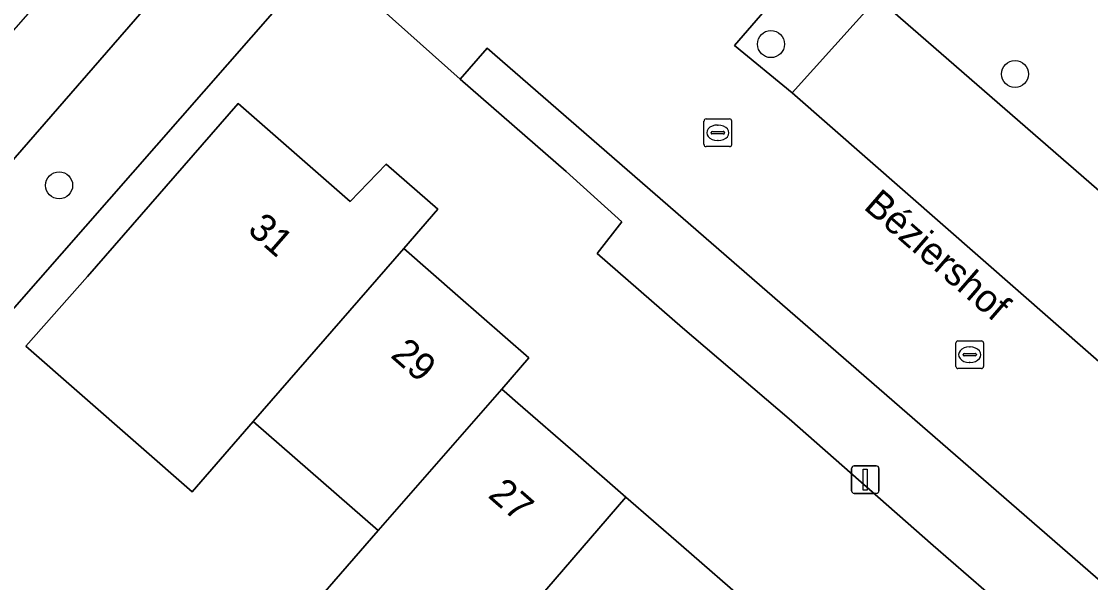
# Model space of a CAD drawing. Extents: x 158472 to 159562, y 388525 to 389606.
# Drawn here: x 158911.21 to 158949.88, y 388805.54 to 388825.82 of the extents above; entities that cross this region are included whole.
import ezdxf

# ---------------------------------------------------------------- set-up
doc = ezdxf.new("R2010")
doc.units = 0
for name, color, linetype in [('IMGEO_Boom', 7, 'Continuous'), ('IMGEO_Erf', 7, 'Continuous'), ('IMGEO_Fietspad_gesloten', 7, 'Continuous'), ('IMGEO_Groenvoorziening', 7, 'Continuous'), ('IMGEO_Haag', 7, 'Continuous'), ('IMGEO_Kolk', 7, 'Continuous'), ('IMGEO_Lichtmast', 7, 'Continuous'), ('IMGEO_Openbare_ruimte_label', 7, 'Continuous'), ('IMGEO_Pand', 7, 'Continuous'), ('IMGEO_Pand_nummerreeks', 7, 'Continuous'), ('IMGEO_Parkeervlak_open', 7, 'Continuous'), ('IMGEO_Rijbaan_lokaal_open', 7, 'Continuous'), ('IMGEO_Voetpad_open', 7, 'Continuous')]:
    doc.layers.add(name, color=color, linetype=linetype)

msp = doc.modelspace()

# ---------------------------------------------------------------- linework, layer by layer
at = {"layer": 'IMGEO_Boom'}
for centre in [(158938.319, 388825.003), (158947.149, 388823.921), (158912.572, 388819.898)]:
    msp.add_circle(centre, 0.489, dxfattribs=at)
at = {"layer": 'IMGEO_Erf'}
for points in [[(158948.022, 388803.56), (158944.187, 388806.882), (158938.98, 388811.457), (158935.123, 388814.752), (158932.03, 388817.43), (158932.924, 388818.579), (158930.914, 388820.395), (158927.08, 388823.739), (158924.182, 388826.315), (158922.086, 388828.178), (158895.45, 388797.816)], [(158920.505, 388803.282), (158924.117, 388807.418), (158919.597, 388811.364), (158917.382, 388808.826), (158911.364, 388814.08), (158913.593, 388816.605), (158919.045, 388822.851), (158923.096, 388819.313), (158924.4, 388820.668), (158926.271, 388819.033), (158925.036, 388817.62), (158926.999, 388815.907), (158929.568, 388813.664), (158928.581, 388812.533), (158928.766, 388812.372), (158929.162, 388812.027), (158931.246, 388810.215), (158933.067, 388808.632), (158935.074, 388806.887), (158937.593, 388804.696)]]:
    msp.add_lwpolyline(points, dxfattribs=at)
at = {"layer": 'IMGEO_Fietspad_gesloten'}
msp.add_lwpolyline([(158939.547, 388858.13), (158926.586, 388843.327), (158908.631, 388822.912), (158891.98, 388803.837), (158886.534, 388797.524), (158886.262, 388797.803), (158884.323, 388795.61), (158883.327, 388794.483), (158872.522, 388782.263), (158876.002, 388779.209), (158877.157, 388780.522), (158889.917, 388795.054), (158889.244, 388795.75), (158891.577, 388798.482), (158892.838, 388800.078), (158918.64, 388829.712), (158922.701, 388834.313), (158925.978, 388838.056), (158929.322, 388841.85), (158932.045, 388844.827), (158941.937, 388856.138)], dxfattribs=at)
at = {"layer": 'IMGEO_Groenvoorziening'}
msp.add_lwpolyline([(158918.64, 388829.712), (158892.838, 388800.078), (158895.45, 388797.816), (158922.086, 388828.178), (158920.255, 388829.805)], dxfattribs=at)
at = {"layer": 'IMGEO_Haag'}
msp.add_lwpolyline([(158918.64, 388829.712), (158892.838, 388800.078), (158895.45, 388797.816), (158922.086, 388828.178), (158920.255, 388829.805)], dxfattribs=at)
at = {"layer": 'IMGEO_Kolk'}
for p, q in [((158935.898, 388821.371), (158935.898, 388822.223)), ((158935.973, 388822.297), (158936.825, 388822.297)), ((158936.386, 388822.077), (158936.411, 388822.077)), ((158936.899, 388822.223), (158936.899, 388821.371)), ((158936.157, 388821.791), (158936.157, 388821.803)), ((158936.595, 388821.754), (158936.197, 388821.754)), ((158936.2, 388821.84), (158936.598, 388821.84)), ((158936.641, 388821.803), (158936.641, 388821.791)), ((158936.825, 388821.297), (158935.973, 388821.297)), ((158936.409, 388821.517), (158936.384, 388821.517)), ((158945.084, 388814.277), (158945.936, 388814.277)), ((158945.009, 388813.351), (158945.009, 388814.203)), ((158945.497, 388814.057), (158945.522, 388814.057)), ((158946.01, 388814.203), (158946.01, 388813.351)), ((158945.268, 388813.771), (158945.268, 388813.783)), ((158945.706, 388813.734), (158945.308, 388813.734)), ((158945.311, 388813.82), (158945.709, 388813.82)), ((158945.52, 388813.497), (158945.495, 388813.497)), ((158945.752, 388813.783), (158945.752, 388813.771)), ((158945.936, 388813.277), (158945.084, 388813.277))]:
    msp.add_line(p, q, dxfattribs=at)
for points in [[(158935.898, 388821.371), (158935.898, 388822.223)], [(158935.973, 388822.297), (158936.825, 388822.297)], [(158936.899, 388822.223), (158936.899, 388821.371)], [(158936.825, 388821.297), (158935.973, 388821.297)], [(158945.084, 388814.277), (158945.936, 388814.277)], [(158945.009, 388813.351), (158945.009, 388814.203)], [(158946.01, 388814.203), (158946.01, 388813.351)], [(158945.936, 388813.277), (158945.084, 388813.277)]]:
    msp.add_lwpolyline(points, dxfattribs=at)
for centre, radius, start, end in [((158935.975, 388822.221), 0.0765, 91.552, 178.448), ((158935.975, 388822.221), 0.0765, 91.552, 178.448), ((158936.823, 388822.221), 0.0765, 1.552, 88.448), ((158936.823, 388822.221), 0.0765, 1.552, 88.448), ((158936.197, 388821.8), 0.0403, 85.8775, 175.7526), ((158936.194, 388821.79), 0.0366, 178.938, 274.7102), ((158936.598, 388821.797), 0.043, 264.8664, 352.4533), ((158936.602, 388821.802), 0.0386, 1.7309, 96.639), ((158935.975, 388821.373), 0.0765, 181.552, 268.448), ((158935.975, 388821.373), 0.0765, 181.552, 268.448), ((158936.823, 388821.373), 0.0765, 271.552, 358.448), ((158936.823, 388821.373), 0.0765, 271.552, 358.448), ((158945.086, 388814.201), 0.0765, 91.552, 178.448), ((158945.086, 388814.201), 0.0765, 91.552, 178.448), ((158945.934, 388814.201), 0.0765, 1.552, 88.448), ((158945.934, 388814.201), 0.0765, 1.552, 88.448), ((158945.308, 388813.78), 0.0403, 85.8775, 175.7526), ((158945.305, 388813.77), 0.0366, 178.938, 274.7102), ((158945.709, 388813.777), 0.043, 264.8664, 352.4533), ((158945.713, 388813.782), 0.0386, 1.7309, 96.639), ((158945.086, 388813.353), 0.0765, 181.552, 268.448), ((158945.086, 388813.353), 0.0765, 181.552, 268.448), ((158945.934, 388813.353), 0.0765, 271.552, 358.448), ((158945.934, 388813.353), 0.0765, 271.552, 358.448)]:
    msp.add_arc(centre, radius, start, end, dxfattribs=at)
for centre, major_axis, ratio, start_param, end_param in [((158936.385, 388821.797), (-0.387, 0.002), 0.722429, 4.712389, 7.853982), ((158936.41, 388821.797), (-0.39, 0.002), 0.717154, 1.570796, 4.712389), ((158945.496, 388813.777), (-0.387, 0.002), 0.722429, 4.712389, 7.853982), ((158945.521, 388813.777), (-0.39, 0.002), 0.717154, 1.570796, 4.712389)]:
    msp.add_ellipse(centre, major_axis=major_axis, ratio=ratio, start_param=start_param, end_param=end_param, dxfattribs=at)
at = {"layer": 'IMGEO_Lichtmast'}
for p, q in [((158941.235, 388808.861), (158941.235, 388809.661)), ((158941.235, 388809.661), (158941.235, 388808.861)), ((158941.335, 388809.761), (158942.125, 388809.761)), ((158942.125, 388809.761), (158941.335, 388809.761)), ((158942.225, 388809.661), (158942.225, 388808.861)), ((158942.225, 388808.861), (158942.225, 388809.661)), ((158942.125, 388808.761), (158941.335, 388808.761)), ((158941.335, 388808.761), (158942.125, 388808.761))]:
    msp.add_line(p, q, dxfattribs=at)
msp.add_lwpolyline([(158941.655, 388809.636), (158941.805, 388809.636), (158941.805, 388808.886), (158941.655, 388808.886), (158941.655, 388809.636)], dxfattribs=at)
for centre, start, end in [((158941.335, 388809.661), 90, 180), ((158941.335, 388809.661), 90, 180), ((158942.125, 388809.661), 0, 90), ((158942.125, 388809.661), 360, 90), ((158941.335, 388808.861), 180, 270), ((158941.335, 388808.861), 180, 270), ((158942.125, 388808.861), 270, 0), ((158942.125, 388808.861), 270, 0)]:
    msp.add_arc(centre, 0.1, start, end, dxfattribs=at)
at = {"layer": 'IMGEO_Pand'}
for points in [[(158926.271, 388819.033), (158924.4, 388820.668), (158923.096, 388819.313), (158919.045, 388822.851), (158913.593, 388816.605), (158911.364, 388814.08), (158917.382, 388808.826), (158919.597, 388811.364), (158925.036, 388817.62)], [(158928.581, 388812.533), (158929.568, 388813.664), (158926.999, 388815.907), (158925.036, 388817.62), (158919.597, 388811.364), (158924.117, 388807.418)], [(158933.067, 388808.632), (158931.246, 388810.215), (158929.162, 388812.027), (158928.766, 388812.372), (158928.581, 388812.533), (158924.117, 388807.418), (158920.505, 388803.282), (158925.042, 388799.336), (158927.663, 388802.35)], [(158937.593, 388804.696), (158935.074, 388806.887), (158933.067, 388808.632), (158927.663, 388802.35), (158925.042, 388799.336), (158922.564, 388796.487), (158927.128, 388792.519), (158929.695, 388795.506)]]:
    msp.add_lwpolyline(points, close=True, dxfattribs=at)
at = {"layer": 'IMGEO_Parkeervlak_open'}
msp.add_lwpolyline([(158939.082, 388823.238), (158955.341, 388809.01), (158958.574, 388812.427), (158942.175, 388826.678)], close=True, dxfattribs=at)
at = {"layer": 'IMGEO_Rijbaan_lokaal_open'}
msp.add_lwpolyline([(158927.054, 388829.223), (158926.892, 388829.365), (158924.182, 388826.315), (158927.08, 388823.739), (158928.05, 388824.862), (158959.175, 388797.838), (158965.788, 388805.265), (158969.246, 388809.149), (158962.92, 388814.631), (158959.478, 388810.733), (158956.854, 388807.76), (158955.341, 388809.01), (158939.082, 388823.238), (158937.005, 388824.955), (158942.646, 388831.471)], dxfattribs=at)
at = {"layer": 'IMGEO_Voetpad_open'}
for points in [[(158930.748, 388841.919), (158934.325, 388838.808), (158937.853, 388835.702), (158942.646, 388831.471), (158937.005, 388824.955), (158939.082, 388823.238), (158942.175, 388826.678), (158958.574, 388812.427), (158955.341, 388809.01), (158956.854, 388807.76), (158959.478, 388810.733), (158962.92, 388814.631), (158969.246, 388809.149), (158965.788, 388805.265), (158969.296, 388802.14), (158970.588, 388801.233), (158972.066, 388799.994), (158973.085, 388801.192), (158975.512, 388804.045), (158976.586, 388805.308), (158975.565, 388806.198), (158975.043, 388806.651), (158969.67, 388811.315), (158964.083, 388816.165)], [(158952.352, 388780.205), (158964.006, 388793.644), (158970.588, 388801.233), (158969.296, 388802.14), (158962.832, 388794.663), (158962.708, 388794.771), (158961.808, 388795.552), (158959.175, 388797.838), (158928.05, 388824.862), (158927.08, 388823.739), (158930.914, 388820.395), (158932.924, 388818.579), (158932.03, 388817.43), (158935.123, 388814.752), (158938.98, 388811.457), (158944.187, 388806.882), (158948.022, 388803.56), (158953.243, 388799.022), (158957.047, 388795.76), (158960.014, 388793.15), (158956.051, 388788.641), (158955.879, 388788.794), (158947.815, 388779.521)]]:
    msp.add_lwpolyline(points, dxfattribs=at)

# ---------------------------------------------------------------- texts
at = {"layer": 'IMGEO_Openbare_ruimte_label'}
msp.add_text('Béziershof', height=1, rotation=319.0135, dxfattribs=at).set_placement((158941.634, 388819.077))
at = {"layer": 'IMGEO_Pand_nummerreeks'}
for s, rotation, p in [('31', 318.8731, (158919.349, 388818.231)), ('29', 318.8788, (158924.525, 388813.711)), ('27', 318.9877, (158928.048, 388808.65))]:
    msp.add_text(s, height=1, rotation=rotation, dxfattribs=at).set_placement(p)

doc.saveas('drawing.dxf')
